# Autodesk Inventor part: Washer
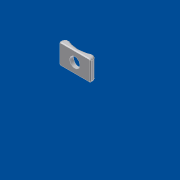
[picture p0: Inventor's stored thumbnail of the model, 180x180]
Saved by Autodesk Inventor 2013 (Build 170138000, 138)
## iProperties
Shininess: 64.0
Length Units: 11269
Angle Units: 11279
Time Units: 11290
Mass Units: 11283
Length Display Precision: 3
Angle Display Precision: 2
Compacted: True
Part Number: Washer
Document SubType Name: Modeling
Created: 2002-10
Designer: roithn
Density: 1 g/cm^3
Material: Generic
Density: 0.0
Volumn: 0.0
Area: 0.0
PropertySet Name: Model Information
Control State: 0
Master: False
Checked Out: False
Author: roithn
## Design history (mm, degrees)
node "Sketch1"
workplane "Work Plane1"
sketch "Sketch2"
  geometry: L1 (-8.177, 16.058)-(9.823, 16.058); L2 (9.823, 16.058)-(9.823, 4.058); L3 (9.823, 4.058)-(-8.177, 4.058); L4 (-8.177, 4.058)-(-8.177, 16.058)
  constraints: 8 end point, 2 parallel, 1 horizontal, 1 perpendicular
  dimensions: "d0" = 18 distance of L1.start L1.end; "d1" = 12 distance of L3.end L1.start
extrude "Extrusion1" new body sketch "Sketch2" distance "d2" = 10; taper "d3" = 0 deg
sketch "Sketch3"
  geometry: L1 (18, 10)-(0, 10) reference; L2 (18, 0)-(18, 10) reference; L3 (9, 10)-(9, 17); C1 r 15 at (9, 17)
  constraints: 2 end point, 1 centre point, 1 coincident, 1 midpoint, 1 parallel
  dimensions: "d4" = 30 diameter of C1; "d5" = 7 distance of L3.start L3.end
extrude "Extrusion2" cut sketch "Sketch3" stored distance "d6" = 10; taper "d7" = 0 deg
fillet "Fillet1" dims "d8" = 2
fillet "Fillet2" dims "d9" = 1
chamfer "Chamfer1" distance "d10" = 0.5; stored, may be unused: second distance "d11" = 2, angle "d23" = 45 deg
sketch "Sketch4"
  geometry: L1 (-7.677, 5.058)-(-7.677, 15.058) reference; L2 (8.823, 4.558)-(-7.177, 4.558) reference; 1 further point
  dimensions: "d12" = 8.5 distance from line of point (0.823, 10.058) L1 (computed from d0); "d13" = 5.5 distance from line of L2 point (0.823, 10.058) (computed from d1)
hole "Hole1" sketch "Sketch4" at (0.823, 10.058) diameter "d14" = 6; stored, may be unused: countersink angle "d18" = 82 deg, drill point angle "d20" = 118 deg; dims "d15" = 6, "d16" = 4, "d17" = 2, "d19" = 8
workaxis "Work Axis1"
body "Solid1"
